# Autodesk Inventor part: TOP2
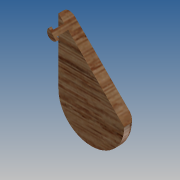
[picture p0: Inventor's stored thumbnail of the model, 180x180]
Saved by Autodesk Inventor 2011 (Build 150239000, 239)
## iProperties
Created: 2011-01
Part Number: TOP2
Document SubType Name: Modeling
Designer: Microsoft
Density: 1 g/cm^3
Author: Microsoft
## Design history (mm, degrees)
sketch "Sketch1"
  geometry: L1 (9.525, 0)-(9.525, 19.05); L2 (-9.525, 19.05)-(-9.525, 0); L3 (-9.525, 19.05)-(9.525, 0); A1 r 9.525 centre (0, 0) between (-9.525, 0) and (9.525, 0); A2 r 9.525 centre (0, 19.05) between (9.525, 19.05) and (-9.525, 19.05); 1 further point
  constraints: 6 end point, 4 point on circle, 3 tangent, 2 centre point, 1 coincident, 1 vertical alignment
  dimensions: "d3" = 9.525 radius of A2; "d4" = 9.525 radius of A1; "d5" = 19.05 distance of L1.start L1.end; "d6" = 19.05 distance of point (0, 0) A2.centre
extrude "Extrusion1" new body sketch "Sketch1" distance "d7" = 19.05; taper "d8" = 0 deg
sketch "Sketch2"
  geometry: L1 (13.47, 0)-(13.47, 19.05) reference; C1 r 0.794 at (13.47, 9.525); 1 further point
  constraints: 1 centre point, 1 midpoint
  dimensions: "d9" = 1.5875 diameter of C1
extrude "Extrusion2" cut sketch "Sketch2" distance "d10" = 6.35; taper "d11" = 0 deg
sketch "Sketch3"
  geometry: C1 r 0.794 at (0, 0) reference; C2 r 1.587 at (0, 0); 1 further point
  constraints: 1 centre point, 1 coincident
  dimensions: "d12" = 3.175 diameter of C2
extrude "Extrusion3" cut sketch "Sketch3" distance "d13" = 0.79375; taper "d14" = 0 deg
workplane "Work Plane1"
sketch "Sketch4"
  geometry: L1 (9.525, 19.05)-(-9.525, 0) reference; L2 (9.525, 0)-(9.525, 19.05) reference; L3 (9.525, 19.05)-(5.927, 22.648); L4 (9.525, 19.05)-(-9.525, 0) reference; C1 r 0.794 at (7.28, 16.805); A1 r 9.525 centre (0, 0) between (-9.525, 0) and (9.525, 0) reference; 1 further point
  constraints: 2 end point, 1 centre point, 1 perpendicular, 1 point on line
  dimensions: "d16" = 1.5875 diameter of C1; "d17" = 3.175 distance from line of L3 C1.centre
extrude "Extrusion4" cut sketch "Sketch4" distance "d18" = 6.35; taper "d19" = 0 deg
sketch "Sketch5"
  geometry: L1 (6.719, 16.244)-(7.841, 17.366) reference; C1 r 1.587 at (7.28, 16.805); A1 r 0.794 centre (7.28, 16.805) between (6.719, 16.244) and (7.841, 17.366) reference; 1 further point
  constraints: 1 centre point, 1 coincident
  dimensions: "d20" = 3.175 diameter of C1
extrude "Extrusion5" cut sketch "Sketch5" distance "d21" = 3.175; taper "d22" = 0 deg
sketch "Sketch6"
  geometry: L1 (-9.525, 0)-(9.525, 19.05) reference; L2 (9.525, 19.05)-(9.525, 0) reference; A1 r 9.525 centre (0, 0) between (-9.525, 0) and (9.525, 0) reference
extrude "Extrusion6" sketch "Sketch6" distance "d23" = 3.175; taper "d24" = 0 deg
fillet "Fillet1" dims "d36" = 2.54
sketch "Sketch10"
  geometry: L1 (9.525, 0)-(-9.525, 19.05); L2 (-9.525, 19.05)-(-6.03, 22.545); A1 r 0.794 centre (-7.28, 16.805) between (-7.841, 17.366) and (-6.719, 16.244)
  constraints: 4 end point, 3 point on line, 2 point on circle, 1 centre point, 1 perpendicular
  dimensions: "d37" = 1.5875 diameter of A1; "d38" = 3.175 distance from line of A1.centre L2
extrude "Extrusion10" join sketch "Sketch10" distance "d39" = 3.175; taper "d40" = 0 deg
sketch "Sketch11"
  geometry: L1 (-7.841, 17.366)-(-6.719, 16.244); L2 (9.525, 0)-(-9.525, 19.05); L3 (-6.157, 15.682)-(-8.402, 17.927); A1 r 0.794 centre (-7.28, 16.805) between (-7.841, 17.366) and (-6.719, 16.244); A2 r 1.587 centre (-7.28, 16.805) between (-8.402, 17.927) and (-6.157, 15.682); 2 further points
  constraints: 6 end point, 4 point on circle, 2 centre point, 2 point on line, 1 coincident
  dimensions: "d41" = 3.175 diameter of A2
extrude "Extrusion11" join sketch "Sketch11" distance "d42" = 0.79375; taper "d43" = 0 deg
sketch "Sketch12"
  geometry: L1 (9.525, 0)-(-6.719, 16.244) reference; L2 (-6.985, 0)-(-9.525, 0) reference; L3 (-7.938, 0)-(-7.937, 15.36); A1 r 9.525 centre (0, 0) between (-9.525, 0) and (9.525, 0) reference; A2 r 1.587 centre (-7.28, 16.805) between (-8.402, 17.927) and (-6.157, 15.682) reference; A3 r 7.938 centre (0, 0) between (-7.938, 0) and (7.732, 1.793)
  constraints: 3 point on circle, 2 end point, 2 point on line, 1 centre point, 1 coincident, 1 perpendicular, 1 tangent
  dimensions: "d44" = 15.875 diameter of A3
extrude "Extrusion12" cut sketch "Sketch12" distance "d45" = 0.79375; taper "d46" = 0 deg
body "Solid1"
node "Projected Loop1"
other parameters: "d15" = -6.35
